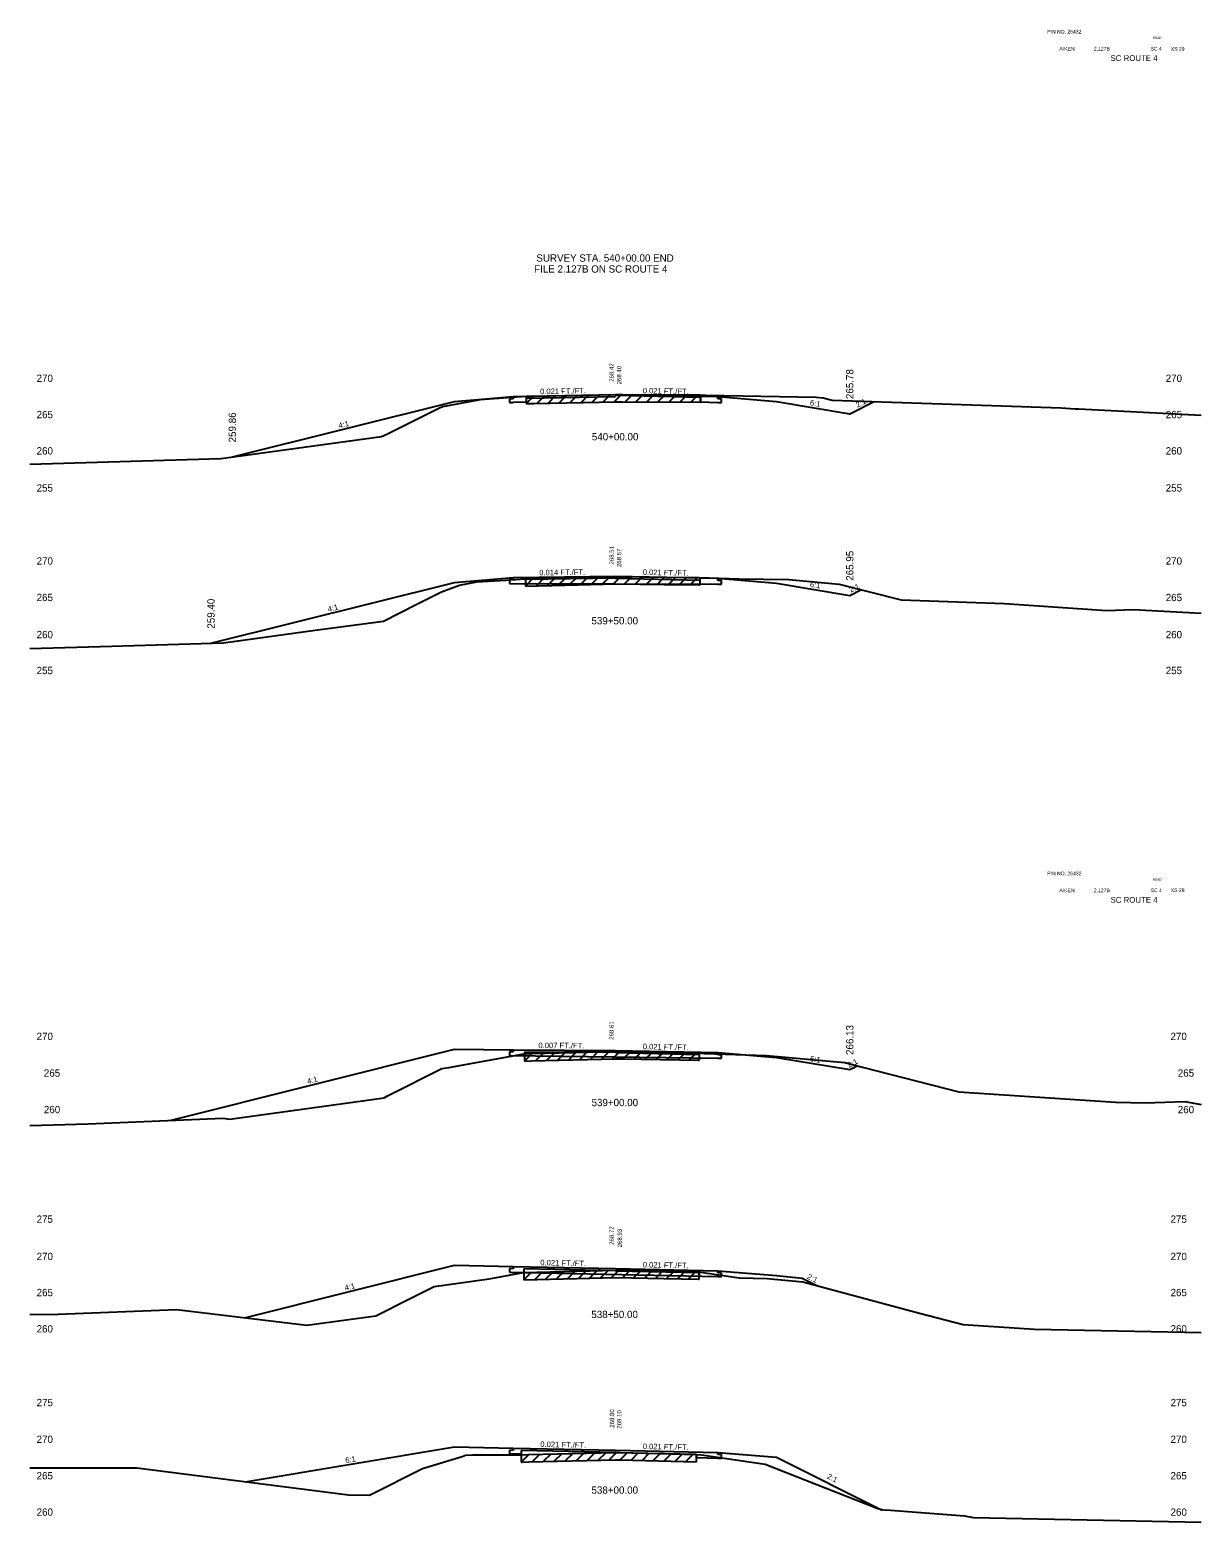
# Model space of a CAD drawing. Extents: x 883 to 1160, y 1002 to 4323.
# Drawn here: x 1000 to 1160, y 4119.3 to 4323.2 of the extents above; entities that cross this region are included whole.
import ezdxf

# ---------------------------------------------------------------- set-up
doc = ezdxf.new("R2010")
doc.units = 0
for name, color, linetype in [('Level 1', 7, 'Continuous'), ('Level 10', 7, 'Continuous'), ('Level 11', 7, 'Continuous'), ('Level 12', 7, 'Continuous'), ('Level 3', 7, 'Continuous'), ('Level 32', 7, 'Continuous'), ('Level 33', 7, 'Continuous'), ('Level 53', 7, 'Continuous'), ('Level 59', 7, 'Continuous'), ('Level 6', 7, 'Continuous'), ('Level 60', 7, 'Continuous'), ('Level 61', 7, 'Continuous'), ('Level 7', 7, 'Continuous')]:
    doc.layers.add(name, color=color, linetype=linetype)

msp = doc.modelspace()

# ---------------------------------------------------------------- linework, layer by layer
at = {"layer": 'Level 11'}
for p, q in [((1066, 4272.81), (1065.5, 4272.8)), ((1065.5, 4272.8), (1065.5, 4272.32)), ((1065.5, 4272.32), (1066, 4272.33)), ((1066, 4273.11), (1066, 4272.81)), ((1094, 4272.81), (1094, 4273.11)), ((1094.5, 4272.8), (1094, 4272.81)), ((1094, 4272.33), (1094.5, 4272.32)), ((1094.5, 4272.32), (1094.5, 4272.8)), ((1066, 4248.08), (1065.5, 4248.07)), ((1065.5, 4248.07), (1065.5, 4247.59)), ((1066, 4248.38), (1066, 4248.08)), ((1094, 4247.98), (1094, 4248.28)), ((1094.5, 4247.97), (1094, 4247.98)), ((1094, 4247.5), (1094.5, 4247.49)), ((1094.5, 4247.49), (1094.5, 4247.97)), ((1066, 4183.54), (1065.5, 4183.55)), ((1065.5, 4183.55), (1065.5, 4183.07)), ((1066, 4183.84), (1066, 4183.54)), ((1094, 4183.16), (1094, 4183.46)), ((1094.5, 4183.15), (1094, 4183.16)), ((1094, 4182.68), (1094.5, 4182.67)), ((1094.5, 4182.67), (1094.5, 4183.15)), ((1066, 4153.92), (1065.5, 4153.93)), ((1065.5, 4153.93), (1065.5, 4153.45)), ((1066, 4154.22), (1066, 4153.92)), ((1094, 4153.33), (1094, 4153.63)), ((1094.5, 4153.32), (1094, 4153.33)), ((1094, 4152.85), (1094.5, 4152.84)), ((1094.5, 4152.84), (1094.5, 4153.32)), ((1066, 4129.09), (1065.5, 4129.1)), ((1065.5, 4129.1), (1065.5, 4128.62)), ((1065.5, 4128.62), (1066, 4128.61)), ((1066, 4129.39), (1066, 4129.09)), ((1094, 4128.51), (1094, 4128.81)), ((1094.5, 4128.5), (1094, 4128.51)), ((1094.5, 4128.02), (1094.5, 4128.5)), ((1094, 4128.03), (1094.5, 4128.02))]:
    msp.add_line(p, q, dxfattribs=at)
at = {"layer": 'Level 12'}
for p, q in [((1067.8, 4273.16), (1067.8, 4272.37)), ((1091.61, 4273.35), (1091.61, 4272.38)), ((1067.8, 4272.37), (1066, 4272.33)), ((1091.61, 4272.38), (1094, 4272.33)), ((1065.5, 4247.59), (1094, 4247.5)), ((1065.5, 4183.07), (1094, 4182.68)), ((1065.5, 4153.45), (1094, 4152.85)), ((1067.46, 4153.4), (1067.46, 4153.41)), ((1091.41, 4153.48), (1091.41, 4152.91)), ((1067.13, 4128.59), (1066, 4128.61)), ((1067.13, 4128.49), (1067.13, 4128.59)), ((1091.08, 4128.54), (1091.08, 4128.09)), ((1091.08, 4128.09), (1094, 4128.03))]:
    msp.add_line(p, q, dxfattribs=at)
at = {"layer": 'Level 53'}
for p, q in [((1080, 4273.29), (1091.61, 4273.05)), ((1080, 4273.1), (1067.8, 4272.85)), ((1080, 4248.28), (1067.69, 4248.1)), ((1080, 4248.28), (1091.55, 4248.03)), ((1080, 4183.45), (1067.57, 4183.53)), ((1067.57, 4183.53), (1067.57, 4183.29)), ((1080, 4183.45), (1091.48, 4183.21)), ((1080, 4153.63), (1067.46, 4153.89)), ((1067.46, 4153.89), (1067.46, 4153.4)), ((1080, 4153.63), (1091.41, 4153.39)), ((1080, 4128.8), (1067.13, 4129.07)), ((1067.13, 4129.07), (1067.13, 4128.49)), ((1080, 4128.8), (1091.08, 4128.57)), ((1091.08, 4128.57), (1091.08, 4128.54))]:
    msp.add_line(p, q, dxfattribs=at)
at = {"layer": 'Level 59'}
for p, q in [((1066, 4273.11), (1080, 4273.4)), ((1080, 4273.4), (1094, 4273.11)), ((1066, 4248.38), (1080, 4248.58)), ((1080, 4248.58), (1094, 4248.28)), ((1066, 4183.84), (1080, 4183.75)), ((1080, 4183.75), (1094, 4183.46)), ((1066, 4154.22), (1080, 4153.93)), ((1080, 4153.93), (1094, 4153.63)), ((1066, 4129.39), (1080, 4129.1)), ((1080, 4129.1), (1094, 4128.81))]:
    msp.add_line(p, q, dxfattribs=at)
at = {"layer": 'Level 6'}
for p, q in [((1058, 4272.44), (1066, 4273.11)), ((1094, 4273.11), (1102, 4272.44)), ((1058, 4247.71), (1066, 4248.38)), ((1094, 4248.28), (1102, 4247.62)), ((1058, 4183.9), (1066, 4183.84)), ((1094, 4183.46), (1102, 4182.79)), ((1058, 4154.38), (1066, 4154.22)), ((1094, 4153.63), (1102, 4152.97)), ((1102, 4152.97), (1105.5, 4152.62)), ((1058, 4129.56), (1066, 4129.39)), ((1094, 4128.81), (1102, 4128.14))]:
    msp.add_line(p, q, dxfattribs=at)
at = {"layer": 'Level 60'}
for p, q in [((1062.12, 4272.78), (1067.8, 4273.16)), ((1067.8, 4273.16), (1068.85, 4273.19)), ((1068.85, 4273.19), (1080.02, 4273.42)), ((1080.02, 4273.42), (1080.96, 4273.4)), ((1080.96, 4273.4), (1091.56, 4273.35)), ((1091.56, 4273.35), (1092.33, 4273.32)), ((1092.33, 4273.32), (1107.41, 4273.03)), ((1048.75, 4268), (1056.03, 4271.64)), ((1056.03, 4271.64), (1056.4, 4271.78)), ((1056.4, 4271.78), (1061.54, 4272.74)), ((1061.54, 4272.74), (1062.12, 4272.78)), ((1107.41, 4273.03), (1108.39, 4272.94)), ((1108.39, 4272.94), (1109.59, 4272.64)), ((1109.59, 4272.64), (1140.87, 4271.57)), ((1140.87, 4271.57), (1142.8, 4271.44)), ((1142.8, 4271.44), (1143.3, 4271.46)), ((1143.3, 4271.46), (1160, 4270.59)), ((1028.15, 4264.92), (1048.05, 4267.64)), ((1048.05, 4267.64), (1048.75, 4268)), ((1000, 4263.89), (1026.08, 4264.64)), ((1026.08, 4264.64), (1028.15, 4264.92)), ((1056.25, 4246.44), (1058.7, 4247.36)), ((1058.7, 4247.36), (1061.06, 4247.8)), ((1061.06, 4247.8), (1065.03, 4248.04)), ((1065.03, 4248.04), (1067.64, 4248.22)), ((1067.64, 4248.22), (1074.91, 4248.41)), ((1074.91, 4248.41), (1080, 4248.51)), ((1080, 4248.51), (1086.64, 4248.42)), ((1086.64, 4248.42), (1091.45, 4248.39)), ((1091.45, 4248.39), (1096.85, 4248.23)), ((1096.85, 4248.23), (1103.68, 4248.1)), ((1103.68, 4248.1), (1110.56, 4247.48)), ((1110.56, 4247.48), (1119.02, 4245.32)), ((1048.3, 4242.44), (1052.88, 4244.75)), ((1052.88, 4244.75), (1056.25, 4246.44)), ((1119.02, 4245.32), (1133.13, 4244.84)), ((1133.13, 4244.84), (1147.14, 4243.9)), ((1147.14, 4243.9), (1150.72, 4244.01)), ((1150.72, 4244.01), (1160, 4243.53)), ((1026.43, 4239.45), (1038.97, 4241.17)), ((1038.97, 4241.17), (1048.3, 4242.44)), ((1000, 4238.69), (1011.18, 4239.01)), ((1011.18, 4239.01), (1026.43, 4239.45)), ((1068.47, 4183.31), (1080, 4183.61)), ((1080, 4183.61), (1080.91, 4183.59)), ((1080.91, 4183.59), (1091.36, 4183.44)), ((1091.36, 4183.44), (1092.16, 4183.32)), ((1056.28, 4181.29), (1057.22, 4181.42)), ((1057.22, 4181.42), (1067.49, 4183.29)), ((1067.49, 4183.29), (1068.47, 4183.31)), ((1092.16, 4183.32), (1100.61, 4183.07)), ((1100.61, 4183.07), (1111.34, 4182.1)), ((1111.34, 4182.1), (1113.72, 4181.45)), ((1113.72, 4181.45), (1126.88, 4178.09)), ((1048.87, 4177.53), (1056.28, 4181.29)), ((1027.33, 4174.36), (1048.39, 4177.28)), ((1048.39, 4177.28), (1048.87, 4177.53)), ((1126.88, 4178.09), (1148.31, 4176.67)), ((1148.31, 4176.67), (1152.35, 4176.59)), ((1152.35, 4176.59), (1157.77, 4176.76)), ((1157.77, 4176.76), (1160, 4176.35)), ((1000, 4173.49), (1007.96, 4173.72)), ((1007.96, 4173.72), (1026.4, 4174.47)), ((1026.4, 4174.47), (1027.33, 4174.36)), ((1062.74, 4152.54), (1067.43, 4153.4)), ((1067.43, 4153.4), (1074.74, 4153.58)), ((1074.74, 4153.58), (1080, 4153.72)), ((1080, 4153.72), (1086.59, 4153.56)), ((1086.59, 4153.56), (1091.34, 4153.49)), ((1091.34, 4153.49), (1096.88, 4152.69)), ((1051.84, 4149.78), (1055.21, 4151.49)), ((1055.21, 4151.49), (1062.74, 4152.54)), ((1096.88, 4152.69), (1100.71, 4152.58)), ((1100.71, 4152.58), (1105.58, 4152.14)), ((1105.58, 4152.14), (1121.52, 4147.82)), ((1047.27, 4147.49), (1051.84, 4149.78)), ((1000, 4147.66), (1003.85, 4147.69)), ((1003.85, 4147.69), (1020.04, 4148.35)), ((1020.04, 4148.35), (1037.82, 4146.18)), ((1037.82, 4146.18), (1047.27, 4147.49)), ((1121.52, 4147.82), (1127.5, 4146.29)), ((1127.5, 4146.29), (1137.24, 4145.65)), ((1137.24, 4145.65), (1160, 4145.19)), ((1059.06, 4128.26), (1059.51, 4128.44)), ((1059.51, 4128.44), (1060.49, 4128.46)), ((1060.49, 4128.46), (1067.15, 4128.49)), ((1067.15, 4128.49), (1068.13, 4128.52)), ((1068.13, 4128.52), (1080, 4128.8)), ((1080, 4128.8), (1080.64, 4128.79)), ((1080.64, 4128.79), (1091.05, 4128.54)), ((1091.05, 4128.54), (1091.77, 4128.47)), ((1091.77, 4128.47), (1100.46, 4127.21)), ((1000, 4126.69), (1013.54, 4126.69)), ((1013.54, 4126.69), (1014.6, 4126.68)), ((1014.6, 4126.68), (1043.54, 4122.99)), ((1046.38, 4122.97), (1053.63, 4126.6)), ((1053.63, 4126.6), (1059.06, 4128.26)), ((1100.46, 4127.21), (1115.83, 4121.16)), ((1043.54, 4122.99), (1046.38, 4122.97)), ((1115.83, 4121.16), (1116.65, 4120.97)), ((1116.65, 4120.97), (1117.58, 4120.93)), ((1117.58, 4120.93), (1127.66, 4120.15)), ((1127.66, 4120.15), (1128.84, 4119.9)), ((1128.84, 4119.9), (1160, 4119.27))]:
    msp.add_line(p, q, dxfattribs=at)
at = {"layer": 'Level 61'}
for p, q in [((1068.83, 4273.19), (1067.8, 4272.16)), ((1067.8, 4273.16), (1067.8, 4272.16)), ((1070.32, 4273.22), (1069.3, 4272.2)), ((1071.82, 4273.25), (1070.8, 4272.23)), ((1073.32, 4273.28), (1072.3, 4272.26)), ((1074.82, 4273.31), (1073.8, 4272.29)), ((1076.32, 4273.34), (1075.3, 4272.32)), ((1077.82, 4273.37), (1076.8, 4272.35)), ((1079.32, 4273.4), (1078.3, 4272.38)), ((1080.8, 4273.4), (1079.8, 4272.41)), ((1082.3, 4273.4), (1081.3, 4272.4)), ((1083.8, 4273.39), (1082.8, 4272.39)), ((1085.3, 4273.38), (1084.3, 4272.39)), ((1086.8, 4273.37), (1085.8, 4272.38)), ((1088.3, 4273.36), (1087.3, 4272.37)), ((1089.8, 4273.36), (1088.8, 4272.36)), ((1091.3, 4273.35), (1090.3, 4272.35)), ((1091.61, 4272.35), (1091.61, 4273.35)), ((1067.8, 4272.16), (1068.85, 4272.19)), ((1068.85, 4272.19), (1080.02, 4272.42)), ((1080.02, 4272.42), (1080.96, 4272.4)), ((1080.96, 4272.4), (1091.56, 4272.35)), ((1091.56, 4272.35), (1091.61, 4272.35)), ((1068.71, 4248.25), (1067.69, 4247.22)), ((1067.69, 4248.22), (1067.69, 4247.22)), ((1067.69, 4247.22), (1074.91, 4247.41)), ((1070.21, 4248.29), (1069.19, 4247.26)), ((1071.71, 4248.32), (1070.69, 4247.3)), ((1073.21, 4248.36), (1072.19, 4247.34)), ((1074.71, 4248.4), (1073.69, 4247.38)), ((1074.91, 4247.41), (1080, 4247.51)), ((1076.21, 4248.43), (1075.19, 4247.41)), ((1077.71, 4248.46), (1076.69, 4247.44)), ((1079.21, 4248.49), (1078.19, 4247.47)), ((1080.68, 4248.5), (1079.69, 4247.5)), ((1080, 4247.51), (1086.64, 4247.42)), ((1082.17, 4248.48), (1081.19, 4247.49)), ((1083.67, 4248.46), (1082.69, 4247.47)), ((1085.17, 4248.44), (1084.19, 4247.45)), ((1086.67, 4248.42), (1085.69, 4247.43)), ((1086.64, 4247.42), (1091.45, 4247.39)), ((1088.18, 4248.41), (1087.19, 4247.41)), ((1089.68, 4248.4), (1088.69, 4247.41)), ((1091.18, 4248.39), (1090.19, 4247.4)), ((1091.45, 4247.39), (1091.55, 4247.39)), ((1091.55, 4247.39), (1091.55, 4248.39)), ((1071.6, 4183.39), (1070.57, 4182.37)), ((1073.1, 4183.43), (1072.07, 4182.4)), ((1074.6, 4183.47), (1073.57, 4182.44)), ((1076.1, 4183.51), (1075.07, 4182.48)), ((1077.6, 4183.55), (1076.57, 4182.52)), ((1079.1, 4183.58), (1078.07, 4182.56)), ((1080.57, 4183.59), (1079.57, 4182.6)), ((1082.06, 4183.57), (1081.07, 4182.58)), ((1083.56, 4183.55), (1082.57, 4182.56)), ((1085.06, 4183.53), (1084.07, 4182.54)), ((1086.56, 4183.51), (1085.57, 4182.52)), ((1088.06, 4183.49), (1087.07, 4182.5)), ((1089.56, 4183.46), (1088.57, 4182.48)), ((1091.06, 4183.44), (1090.07, 4182.46)), ((1091.48, 4182.42), (1091.48, 4183.42)), ((1068.6, 4183.32), (1067.57, 4182.29)), ((1067.57, 4183.29), (1067.57, 4182.29)), ((1067.57, 4182.29), (1068.47, 4182.31)), ((1068.47, 4182.31), (1080, 4182.61)), ((1070.1, 4183.35), (1069.07, 4182.33)), ((1080, 4182.61), (1080.91, 4182.59)), ((1080.91, 4182.59), (1091.36, 4182.44)), ((1091.36, 4182.44), (1091.48, 4182.42)), ((1068.49, 4153.42), (1067.46, 4152.4)), ((1067.46, 4153.4), (1067.46, 4152.4)), ((1069.99, 4153.46), (1068.96, 4152.44)), ((1071.49, 4153.5), (1070.46, 4152.47)), ((1072.99, 4153.54), (1071.96, 4152.51)), ((1074.49, 4153.58), (1073.46, 4152.55)), ((1075.99, 4153.62), (1074.96, 4152.59)), ((1077.49, 4153.65), (1076.46, 4152.63)), ((1078.99, 4153.69), (1077.96, 4152.67)), ((1080.46, 4153.71), (1079.46, 4152.7)), ((1081.94, 4153.67), (1080.96, 4152.69)), ((1083.44, 4153.64), (1082.46, 4152.66)), ((1084.94, 4153.6), (1083.96, 4152.62)), ((1086.44, 4153.56), (1085.46, 4152.59)), ((1087.95, 4153.54), (1086.96, 4152.56)), ((1089.45, 4153.52), (1088.46, 4152.53)), ((1090.95, 4153.5), (1089.96, 4152.51)), ((1091.41, 4152.48), (1091.41, 4153.48)), ((1067.46, 4152.4), (1074.74, 4152.58)), ((1074.74, 4152.58), (1080, 4152.72)), ((1080, 4152.72), (1086.59, 4152.56)), ((1086.59, 4152.56), (1091.34, 4152.49)), ((1091.34, 4152.49), (1091.41, 4152.48)), ((1068.15, 4128.52), (1067.13, 4127.49)), ((1067.13, 4128.49), (1067.13, 4127.49)), ((1069.66, 4128.55), (1068.63, 4127.53)), ((1071.16, 4128.59), (1070.13, 4127.56)), ((1072.66, 4128.63), (1071.63, 4127.6)), ((1074.16, 4128.66), (1073.13, 4127.64)), ((1075.66, 4128.7), (1074.63, 4127.67)), ((1077.16, 4128.74), (1076.13, 4127.71)), ((1078.66, 4128.77), (1077.63, 4127.75)), ((1080.15, 4128.8), (1079.13, 4127.78)), ((1081.61, 4128.77), (1080.63, 4127.79)), ((1083.11, 4128.73), (1082.13, 4127.76)), ((1084.61, 4128.7), (1083.63, 4127.72)), ((1086.11, 4128.66), (1085.13, 4127.69)), ((1087.61, 4128.63), (1086.63, 4127.65)), ((1089.11, 4128.59), (1088.13, 4127.61)), ((1090.61, 4128.55), (1089.63, 4127.58)), ((1091.08, 4127.54), (1091.08, 4128.54)), ((1067.13, 4127.49), (1067.15, 4127.49)), ((1067.15, 4127.49), (1068.13, 4127.52)), ((1068.13, 4127.52), (1080, 4127.8)), ((1080, 4127.8), (1080.64, 4127.79)), ((1080.64, 4127.79), (1091.05, 4127.54)), ((1091.05, 4127.54), (1091.08, 4127.54))]:
    msp.add_line(p, q, dxfattribs=at)
at = {"layer": 'Level 7'}
for p, q in [((1027.66, 4264.86), (1058, 4272.44)), ((1102, 4272.44), (1112, 4270.78)), ((1112, 4270.78), (1115.33, 4272.44)), ((1024.74, 4239.4), (1058, 4247.71)), ((1102, 4247.62), (1112, 4245.95)), ((1112, 4245.95), (1113.53, 4246.72)), ((1019.1, 4174.17), (1058, 4183.9)), ((1102, 4182.79), (1112, 4181.13)), ((1112, 4181.13), (1113.03, 4181.64)), ((1029.33, 4147.22), (1058, 4154.38)), ((1105.5, 4152.62), (1107.5, 4151.62)), ((1029.42, 4124.79), (1058, 4129.56)), ((1102, 4128.14), (1116.43, 4120.93))]:
    msp.add_line(p, q, dxfattribs=at)

# ---------------------------------------------------------------- texts
at = {"layer": 'Level 1'}
for s, height, p in [('PIN NO. 26432', 0.5, (1138.97, 4322.74)), ('AIKEN', 0.5, (1140.64, 4320.42)), (' 2.127B', 0.5, (1145.15, 4320.42)), ('SC 4', 0.5, (1153.09, 4320.42)), ('XS 29', 0.5, (1155.85, 4320.39)), ('SC ROUTE 4', 0.8, (1147.63, 4318.98)), ('SURVEY STA. 540+00.00 END', 1, (1069.19, 4291.56)), (' FILE 2.127B ON SC ROUTE 4 ', 1, (1068.51, 4290.06)), ('540+00.00', 1, (1076.77, 4267.13)), ('539+50.00', 1, (1076.72, 4241.98)), ('PIN NO. 26432', 0.5, (1138.97, 4207.69)), ('AIKEN', 0.5, (1140.64, 4205.38)), (' 2.127B', 0.5, (1145.15, 4205.38)), ('SC 4', 0.5, (1153.09, 4205.38)), ('XS 28', 0.5, (1155.85, 4205.4)), ('SC ROUTE 4', 0.8, (1147.63, 4203.93)), ('539+00.00', 1, (1076.73, 4176.13)), ('538+50.00', 1, (1076.7, 4147.17)), ('538+00.00', 1, (1076.72, 4123.16))]:
    msp.add_text(s, height=height, dxfattribs=at).set_placement(p)
at = {"layer": 'Level 10'}
for s, p in [('268.42', (1079.76, 4275.13)), ('268.51', (1079.76, 4250.16)), ('268.61', (1079.76, 4185.2)), ('268.72', (1079.76, 4157.17)), ('268.80', (1079.82, 4132.17))]:
    msp.add_text(s, height=0.6, rotation=90, dxfattribs=at).set_placement(p)
at = {"layer": 'Level 3'}
for s, height, p in [('ROAD', 0.3, (1153.38, 4322.01)), (' 270', 1, (1000.55, 4275.12)), (' 270', 1, (1154.79, 4275.12)), (' 265', 1, (1000.55, 4270.16)), (' 265', 1, (1154.79, 4270.16)), (' 260', 1, (1000.55, 4265.2)), (' 260', 1, (1154.79, 4265.2)), (' 255', 1, (1000.55, 4260.13)), (' 255', 1, (1154.79, 4260.13)), (' 270', 1, (1000.55, 4250.15)), (' 270', 1, (1154.79, 4250.15)), (' 265', 1, (1000.55, 4245.16)), (' 265', 1, (1154.79, 4245.16)), (' 260', 1, (1000.55, 4240.09)), (' 260', 1, (1154.79, 4240.09)), (' 255', 1, (1000.55, 4235.18)), (' 255', 1, (1154.79, 4235.18)), ('ROAD', 0.3, (1153.38, 4206.96)), (' 270', 1, (1000.55, 4185.17)), (' 270', 1, (1155.45, 4185.17)), (' 265', 1, (1001.54, 4180.16)), (' 265', 1, (1156.44, 4180.16)), (' 260', 1, (1001.54, 4175.17)), (' 260', 1, (1156.44, 4175.17)), (' 275', 1, (1000.55, 4160.19)), (' 275', 1, (1155.45, 4160.19)), (' 270', 1, (1000.55, 4155.09)), (' 270', 1, (1155.45, 4155.09)), (' 265', 1, (1000.55, 4150.16)), (' 265', 1, (1155.45, 4150.16)), (' 260', 1, (1000.55, 4145.2)), (' 260', 1, (1155.45, 4145.2)), (' 275', 1, (1000.55, 4135.12)), (' 275', 1, (1155.45, 4135.12)), (' 270', 1, (1000.55, 4130.1)), (' 270', 1, (1155.45, 4130.1)), (' 265', 1, (1000.55, 4125.12)), (' 265', 1, (1155.45, 4125.12)), (' 260', 1, (1000.55, 4120.15)), (' 260', 1, (1155.45, 4120.15))]:
    msp.add_text(s, height=height, dxfattribs=at).set_placement(p)
at = {"layer": 'Level 32'}
for s, rotation, p in [('0.021 FT./FT.', 1.1916, (1069.71, 4273.44)), ('0.021 FT./FT.', 358.8084, (1083.72, 4273.57)), ('6:1', 350.5377, (1106.52, 4271.94)), ('2:1', 26.5651, (1113.05, 4271.58)), ('4:1', 14.0362, (1042.26, 4268.76)), ('0.014 FT./FT.', 0.8054, (1069.59, 4248.68)), ('0.021 FT./FT.', 358.8084, (1083.72, 4248.75)), ('6:1', 350.5377, (1106.52, 4247.12)), ('2:1', 26.5651, (1112.15, 4246.3)), ('4:1', 14.0362, (1040.79, 4243.67)), ('0.007 FT./FT.', 359.6137, (1069.47, 4184.07)), ('0.021 FT./FT.', 358.8084, (1083.72, 4183.92)), ('6:1', 350.5377, (1106.52, 4182.29)), ('2:1', 26.5651, (1111.9, 4181.35)), ('4:1', 14.0362, (1037.97, 4179.15)), ('0.021 FT./FT.', 358.8084, (1069.72, 4154.39)), ('0.021 FT./FT.', 358.8084, (1083.72, 4154.1)), ('2:1', 333.435, (1106.1, 4152.59)), ('4:1', 14.0362, (1043.09, 4150.91)), ('0.021 FT./FT.', 358.8084, (1069.72, 4129.56)), ('0.021 FT./FT.', 358.8084, (1083.72, 4129.27)), ('6:1', 9.4623, (1043.14, 4127.34)), ('2:1', 333.435, (1108.81, 4125.3))]:
    msp.add_text(s, height=0.75, rotation=rotation, dxfattribs=at).set_placement(p)
at = {"layer": 'Level 33'}
for s, p in [('265.78', (1112.5, 4272.78)), ('259.86', (1028.16, 4266.86)), ('265.95', (1112.5, 4247.95)), ('259.40', (1025.24, 4241.4)), ('266.13', (1112.5, 4183.13))]:
    msp.add_text(s, height=1, rotation=90, dxfattribs=at).set_placement(p)
at = {"layer": 'Level 59'}
for s, p in [(' 268.40', (1080.79, 4274.55)), (' 268.57', (1080.79, 4249.58)), (' 268.93', (1080.88, 4156.6)), (' 269.10', (1080.8, 4131.81))]:
    msp.add_text(s, height=0.6, rotation=90, dxfattribs=at).set_placement(p)

doc.saveas('drawing.dxf')
